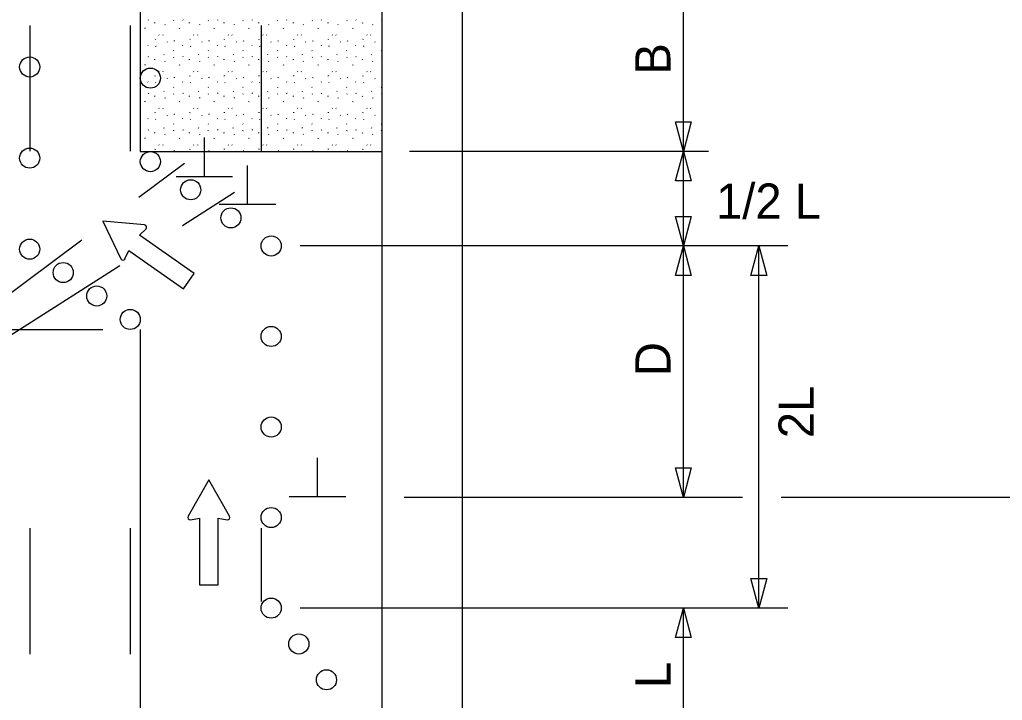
# Model space of a CAD drawing. Extents: x 16748 to 18475, y 7008 to 8262.
# Drawn here: x 17041.1 to 17236.5, y 7634.3 to 7769.6 of the extents above; entities that cross this region are included whole.
import ezdxf

# ---------------------------------------------------------------- set-up
doc = ezdxf.new("R2010")
doc.units = 0
for name, color, linetype in [('ALI_LEGAL_EX', 7, 'Continuous'), ('MT_SCRATCH_LEVEL_A', 7, 'Continuous'), ('MT_SCRATCH_LEVEL_E', 7, 'Continuous'), ('PAVT_EDGE_EX', 7, 'Continuous'), ('TRAFFIC_SIGNS_PR', 7, 'Continuous'), ('TYPICAL_TEXT_DIMEN_PR', 7, 'Continuous')]:
    doc.layers.add(name, color=color, linetype=linetype)

msp = doc.modelspace()

# ---------------------------------------------------------------- linework, layer by layer
at = {"layer": 'ALI_LEGAL_EX'}
for points in [[(17043.08, 7768.47), (17043.08, 7743.47)], [(17063.08, 7768.47), (17063.08, 7743.47)], [(17089.08, 7768.47), (17089.08, 7743.47)], [(17043.08, 7668.47), (17043.08, 7643.47)], [(17063.08, 7668.47), (17063.08, 7643.47)], [(17089.08, 7668.47), (17089.08, 7653.92)]]:
    msp.add_lwpolyline(points, dxfattribs=at)
at = {"layer": 'MT_SCRATCH_LEVEL_A'}
for p, q in [((17066.63, 7769.59), (17066.68, 7769.51)), ((17067.91, 7769.01), (17067.92, 7768.89)), ((17069.94, 7768.67), (17069.99, 7768.59)), ((17071.72, 7769.34), (17071.77, 7769.45)), ((17073.51, 7769.59), (17073.57, 7769.51)), ((17074.8, 7769.01), (17074.81, 7768.89)), ((17076.83, 7768.67), (17076.88, 7768.59)), ((17078.6, 7769.34), (17078.66, 7769.45)), ((17080.4, 7769.59), (17080.45, 7769.51)), ((17081.68, 7769.01), (17081.7, 7768.89)), ((17083.71, 7768.67), (17083.76, 7768.59)), ((17085.49, 7769.34), (17085.54, 7769.45)), ((17087.29, 7769.59), (17087.34, 7769.51)), ((17088.57, 7769.01), (17088.58, 7768.89)), ((17090.6, 7768.67), (17090.65, 7768.59)), ((17092.38, 7769.34), (17092.43, 7769.45)), ((17094.18, 7769.59), (17094.23, 7769.51)), ((17095.46, 7769.01), (17095.47, 7768.89)), ((17097.49, 7768.67), (17097.54, 7768.59)), ((17099.27, 7769.34), (17099.32, 7769.45)), ((17101.06, 7769.59), (17101.12, 7769.51)), ((17102.35, 7769.01), (17102.36, 7768.89)), ((17104.38, 7768.67), (17104.43, 7768.59)), ((17106.15, 7769.34), (17106.21, 7769.45)), ((17107.95, 7769.59), (17108, 7769.51)), ((17109.23, 7769.01), (17109.25, 7768.89)), ((17111.26, 7768.67), (17111.31, 7768.59)), ((17113.04, 7769.34), (17113.1, 7769.45)), ((17066.01, 7767.83), (17066.06, 7767.95)), ((17068.79, 7766.6), (17068.84, 7766.52)), ((17069.53, 7766.57), (17069.58, 7766.49)), ((17072.9, 7767.83), (17072.95, 7767.95)), ((17075.68, 7766.6), (17075.73, 7766.52)), ((17076.42, 7766.57), (17076.47, 7766.49)), ((17079.78, 7767.83), (17079.83, 7767.95)), ((17082.57, 7766.6), (17082.62, 7766.52)), ((17083.3, 7766.57), (17083.36, 7766.49)), ((17086.67, 7767.83), (17086.72, 7767.95)), ((17089.46, 7766.6), (17089.51, 7766.52)), ((17090.19, 7766.57), (17090.24, 7766.49)), ((17093.56, 7767.83), (17093.61, 7767.95)), ((17096.34, 7766.6), (17096.39, 7766.52)), ((17097.08, 7766.57), (17097.13, 7766.49)), ((17100.45, 7767.83), (17100.5, 7767.95)), ((17103.23, 7766.6), (17103.28, 7766.52)), ((17103.97, 7766.57), (17104.02, 7766.49)), ((17107.33, 7767.83), (17107.39, 7767.95)), ((17110.12, 7766.6), (17110.17, 7766.52)), ((17110.85, 7766.57), (17110.91, 7766.49)), ((17066.58, 7764.51), (17066.63, 7764.43)), ((17068.03, 7765.64), (17068.08, 7765.75)), ((17068.11, 7764.37), (17068.16, 7764.29)), ((17070.4, 7765.19), (17070.45, 7765.11)), ((17071.85, 7765.34), (17071.9, 7765.46)), ((17073.47, 7764.51), (17073.52, 7764.43)), ((17074.92, 7765.64), (17074.97, 7765.75)), ((17075, 7764.37), (17075.05, 7764.29)), ((17077.28, 7765.19), (17077.34, 7765.11)), ((17078.74, 7765.34), (17078.79, 7765.46)), ((17080.35, 7764.51), (17080.4, 7764.43)), ((17081.8, 7765.64), (17081.85, 7765.75)), ((17081.88, 7764.37), (17081.94, 7764.29)), ((17084.17, 7765.19), (17084.22, 7765.11)), ((17085.62, 7765.34), (17085.67, 7765.46)), ((17087.24, 7764.51), (17087.29, 7764.43)), ((17088.69, 7765.64), (17088.74, 7765.75)), ((17088.77, 7764.37), (17088.82, 7764.29)), ((17091.06, 7765.19), (17091.11, 7765.11)), ((17092.51, 7765.34), (17092.56, 7765.46)), ((17094.13, 7764.51), (17094.18, 7764.43)), ((17095.58, 7765.64), (17095.63, 7765.75)), ((17095.66, 7764.37), (17095.71, 7764.29)), ((17097.95, 7765.19), (17098, 7765.11)), ((17099.4, 7765.34), (17099.45, 7765.46)), ((17101.02, 7764.51), (17101.07, 7764.43)), ((17102.47, 7765.64), (17102.52, 7765.75)), ((17102.55, 7764.37), (17102.6, 7764.29)), ((17104.84, 7765.19), (17104.89, 7765.11)), ((17106.28, 7765.34), (17106.34, 7765.46)), ((17107.9, 7764.51), (17107.96, 7764.43)), ((17109.35, 7765.64), (17109.4, 7765.75)), ((17109.43, 7764.37), (17109.49, 7764.29)), ((17111.72, 7765.19), (17111.78, 7765.11)), ((17069.75, 7762.58), (17069.8, 7762.7)), ((17071.67, 7763.45), (17071.73, 7763.37)), ((17076.64, 7762.58), (17076.69, 7762.7)), ((17078.56, 7763.45), (17078.61, 7763.37)), ((17083.53, 7762.58), (17083.58, 7762.7)), ((17085.45, 7763.45), (17085.5, 7763.37)), ((17090.41, 7762.58), (17090.46, 7762.7)), ((17092.34, 7763.45), (17092.39, 7763.37)), ((17097.3, 7762.58), (17097.35, 7762.7)), ((17099.22, 7763.45), (17099.28, 7763.37)), ((17104.19, 7762.58), (17104.24, 7762.7)), ((17106.11, 7763.45), (17106.16, 7763.37)), ((17111.08, 7762.58), (17111.13, 7762.7)), ((17113, 7763.45), (17113.05, 7763.37)), ((17066.01, 7760.55), (17066.06, 7760.67)), ((17066.63, 7762.3), (17066.68, 7762.22)), ((17067.91, 7761.73), (17067.92, 7761.61)), ((17069.94, 7761.38), (17069.99, 7761.31)), ((17071.72, 7762.05), (17071.77, 7762.17)), ((17072.9, 7760.55), (17072.95, 7760.67)), ((17073.51, 7762.3), (17073.57, 7762.22)), ((17074.8, 7761.73), (17074.81, 7761.61)), ((17076.83, 7761.38), (17076.88, 7761.31)), ((17078.6, 7762.05), (17078.66, 7762.17)), ((17079.78, 7760.55), (17079.83, 7760.67)), ((17080.4, 7762.3), (17080.45, 7762.22)), ((17081.68, 7761.73), (17081.7, 7761.61)), ((17083.71, 7761.38), (17083.76, 7761.31)), ((17085.49, 7762.05), (17085.54, 7762.17)), ((17086.67, 7760.55), (17086.72, 7760.67)), ((17087.29, 7762.3), (17087.34, 7762.22)), ((17088.57, 7761.73), (17088.58, 7761.61)), ((17090.6, 7761.38), (17090.65, 7761.31)), ((17092.38, 7762.05), (17092.43, 7762.17)), ((17093.56, 7760.55), (17093.61, 7760.67)), ((17094.18, 7762.3), (17094.23, 7762.22)), ((17095.46, 7761.73), (17095.47, 7761.61)), ((17097.49, 7761.38), (17097.54, 7761.31)), ((17099.27, 7762.05), (17099.32, 7762.17)), ((17100.45, 7760.55), (17100.5, 7760.67)), ((17101.06, 7762.3), (17101.12, 7762.22)), ((17102.35, 7761.73), (17102.36, 7761.61)), ((17104.38, 7761.38), (17104.43, 7761.31)), ((17106.15, 7762.05), (17106.21, 7762.17)), ((17107.33, 7760.55), (17107.39, 7760.67)), ((17107.95, 7762.3), (17108, 7762.22)), ((17109.23, 7761.73), (17109.25, 7761.61)), ((17111.26, 7761.38), (17111.31, 7761.31)), ((17113.04, 7762.05), (17113.1, 7762.17)), ((17068.79, 7759.31), (17068.84, 7759.24)), ((17069.53, 7759.28), (17069.58, 7759.2)), ((17075.68, 7759.31), (17075.73, 7759.24)), ((17076.42, 7759.28), (17076.47, 7759.2)), ((17082.57, 7759.31), (17082.62, 7759.24)), ((17083.3, 7759.28), (17083.36, 7759.2)), ((17089.46, 7759.31), (17089.51, 7759.24)), ((17090.19, 7759.28), (17090.24, 7759.2)), ((17096.34, 7759.31), (17096.39, 7759.24)), ((17097.08, 7759.28), (17097.13, 7759.2)), ((17103.23, 7759.31), (17103.28, 7759.24)), ((17103.97, 7759.28), (17104.02, 7759.2)), ((17110.12, 7759.31), (17110.17, 7759.24)), ((17110.85, 7759.28), (17110.91, 7759.2)), ((17066.58, 7757.23), (17066.63, 7757.15)), ((17068.03, 7758.35), (17068.08, 7758.47)), ((17068.11, 7757.09), (17068.16, 7757.01)), ((17070.4, 7757.9), (17070.45, 7757.83)), ((17071.85, 7758.06), (17071.9, 7758.17)), ((17073.47, 7757.23), (17073.52, 7757.15)), ((17074.92, 7758.35), (17074.97, 7758.47)), ((17075, 7757.09), (17075.05, 7757.01)), ((17077.28, 7757.9), (17077.34, 7757.83)), ((17078.74, 7758.06), (17078.79, 7758.17)), ((17080.35, 7757.23), (17080.4, 7757.15)), ((17081.8, 7758.35), (17081.85, 7758.47)), ((17081.88, 7757.09), (17081.94, 7757.01)), ((17084.17, 7757.9), (17084.22, 7757.83)), ((17085.62, 7758.06), (17085.67, 7758.17)), ((17087.24, 7757.23), (17087.29, 7757.15)), ((17088.69, 7758.35), (17088.74, 7758.47)), ((17088.77, 7757.09), (17088.82, 7757.01)), ((17091.06, 7757.9), (17091.11, 7757.83)), ((17092.51, 7758.06), (17092.56, 7758.17)), ((17094.13, 7757.23), (17094.18, 7757.15)), ((17095.58, 7758.35), (17095.63, 7758.47)), ((17095.66, 7757.09), (17095.71, 7757.01)), ((17097.95, 7757.9), (17098, 7757.83)), ((17099.4, 7758.06), (17099.45, 7758.17)), ((17101.02, 7757.23), (17101.07, 7757.15)), ((17102.47, 7758.35), (17102.52, 7758.47)), ((17102.55, 7757.09), (17102.6, 7757.01)), ((17104.84, 7757.9), (17104.89, 7757.83)), ((17106.28, 7758.06), (17106.34, 7758.17)), ((17107.9, 7757.23), (17107.96, 7757.15)), ((17109.35, 7758.35), (17109.4, 7758.47)), ((17109.43, 7757.09), (17109.49, 7757.01)), ((17111.72, 7757.9), (17111.78, 7757.83)), ((17066.63, 7755.02), (17066.68, 7754.94)), ((17069.75, 7755.3), (17069.8, 7755.41)), ((17071.67, 7756.17), (17071.73, 7756.09)), ((17071.72, 7754.77), (17071.77, 7754.88)), ((17073.51, 7755.02), (17073.57, 7754.94)), ((17076.64, 7755.3), (17076.69, 7755.41)), ((17078.56, 7756.17), (17078.61, 7756.09)), ((17078.6, 7754.77), (17078.66, 7754.88)), ((17080.4, 7755.02), (17080.45, 7754.94)), ((17083.53, 7755.3), (17083.58, 7755.41)), ((17085.45, 7756.17), (17085.5, 7756.09)), ((17085.49, 7754.77), (17085.54, 7754.88)), ((17087.29, 7755.02), (17087.34, 7754.94)), ((17090.41, 7755.3), (17090.46, 7755.41)), ((17092.34, 7756.17), (17092.39, 7756.09)), ((17092.38, 7754.77), (17092.43, 7754.88)), ((17094.18, 7755.02), (17094.23, 7754.94)), ((17097.3, 7755.3), (17097.35, 7755.41)), ((17099.22, 7756.17), (17099.28, 7756.09)), ((17099.27, 7754.77), (17099.32, 7754.88)), ((17101.06, 7755.02), (17101.12, 7754.94)), ((17104.19, 7755.3), (17104.24, 7755.41)), ((17106.11, 7756.17), (17106.16, 7756.09)), ((17106.15, 7754.77), (17106.21, 7754.88)), ((17107.95, 7755.02), (17108, 7754.94)), ((17111.08, 7755.3), (17111.13, 7755.41)), ((17113, 7756.17), (17113.05, 7756.09)), ((17113.04, 7754.77), (17113.1, 7754.88)), ((17066.01, 7753.26), (17066.06, 7753.38)), ((17067.91, 7754.44), (17067.92, 7754.32)), ((17069.94, 7754.1), (17069.99, 7754.02)), ((17072.9, 7753.26), (17072.95, 7753.38)), ((17074.8, 7754.44), (17074.81, 7754.32)), ((17076.83, 7754.1), (17076.88, 7754.02)), ((17079.78, 7753.26), (17079.83, 7753.38)), ((17081.68, 7754.44), (17081.7, 7754.32)), ((17083.71, 7754.1), (17083.76, 7754.02)), ((17086.67, 7753.26), (17086.72, 7753.38)), ((17088.57, 7754.44), (17088.58, 7754.32)), ((17090.6, 7754.1), (17090.65, 7754.02)), ((17093.56, 7753.26), (17093.61, 7753.38)), ((17095.46, 7754.44), (17095.47, 7754.32)), ((17097.49, 7754.1), (17097.54, 7754.02)), ((17100.45, 7753.26), (17100.5, 7753.38)), ((17102.35, 7754.44), (17102.36, 7754.32)), ((17104.38, 7754.1), (17104.43, 7754.02)), ((17107.33, 7753.26), (17107.39, 7753.38)), ((17109.23, 7754.44), (17109.25, 7754.32)), ((17111.26, 7754.1), (17111.31, 7754.02)), ((17068.03, 7751.07), (17068.08, 7751.18)), ((17068.79, 7752.03), (17068.84, 7751.95)), ((17069.53, 7752), (17069.58, 7751.92)), ((17071.85, 7750.77), (17071.9, 7750.89)), ((17074.92, 7751.07), (17074.97, 7751.18)), ((17075.68, 7752.03), (17075.73, 7751.95)), ((17076.42, 7752), (17076.47, 7751.92)), ((17078.74, 7750.77), (17078.79, 7750.89)), ((17081.8, 7751.07), (17081.85, 7751.18)), ((17082.57, 7752.03), (17082.62, 7751.95)), ((17083.3, 7752), (17083.36, 7751.92)), ((17085.62, 7750.77), (17085.67, 7750.89)), ((17088.69, 7751.07), (17088.74, 7751.18)), ((17089.46, 7752.03), (17089.51, 7751.95)), ((17090.19, 7752), (17090.24, 7751.92)), ((17092.51, 7750.77), (17092.56, 7750.89)), ((17095.58, 7751.07), (17095.63, 7751.18)), ((17096.34, 7752.03), (17096.39, 7751.95)), ((17097.08, 7752), (17097.13, 7751.92)), ((17099.4, 7750.77), (17099.45, 7750.89)), ((17102.47, 7751.07), (17102.52, 7751.18)), ((17103.23, 7752.03), (17103.28, 7751.95)), ((17103.97, 7752), (17104.02, 7751.92)), ((17106.28, 7750.77), (17106.34, 7750.89)), ((17109.35, 7751.07), (17109.4, 7751.18)), ((17110.12, 7752.03), (17110.17, 7751.95)), ((17110.85, 7752), (17110.91, 7751.92)), ((17066.58, 7749.94), (17066.63, 7749.86)), ((17068.11, 7749.8), (17068.16, 7749.72)), ((17070.4, 7750.62), (17070.45, 7750.54)), ((17071.67, 7748.88), (17071.73, 7748.8)), ((17073.47, 7749.94), (17073.52, 7749.86)), ((17075, 7749.8), (17075.05, 7749.72)), ((17077.28, 7750.62), (17077.34, 7750.54)), ((17078.56, 7748.88), (17078.61, 7748.8)), ((17080.35, 7749.94), (17080.4, 7749.86)), ((17081.88, 7749.8), (17081.94, 7749.72)), ((17084.17, 7750.62), (17084.22, 7750.54)), ((17085.45, 7748.88), (17085.5, 7748.8)), ((17087.24, 7749.94), (17087.29, 7749.86)), ((17088.77, 7749.8), (17088.82, 7749.72)), ((17091.06, 7750.62), (17091.11, 7750.54)), ((17092.34, 7748.88), (17092.39, 7748.8)), ((17094.13, 7749.94), (17094.18, 7749.86)), ((17095.66, 7749.8), (17095.71, 7749.72)), ((17097.95, 7750.62), (17098, 7750.54)), ((17099.22, 7748.88), (17099.28, 7748.8)), ((17101.02, 7749.94), (17101.07, 7749.86)), ((17102.55, 7749.8), (17102.6, 7749.72)), ((17104.84, 7750.62), (17104.89, 7750.54)), ((17106.11, 7748.88), (17106.16, 7748.8)), ((17107.9, 7749.94), (17107.96, 7749.86)), ((17109.43, 7749.8), (17109.49, 7749.72)), ((17111.72, 7750.62), (17111.78, 7750.54)), ((17113, 7748.88), (17113.05, 7748.8)), ((17066.63, 7747.73), (17066.68, 7747.65)), ((17067.91, 7747.16), (17067.92, 7747.04)), ((17069.75, 7748.01), (17069.8, 7748.13)), ((17069.94, 7746.81), (17069.99, 7746.74)), ((17071.72, 7747.48), (17071.77, 7747.6)), ((17073.51, 7747.73), (17073.57, 7747.65)), ((17074.8, 7747.16), (17074.81, 7747.04)), ((17076.64, 7748.01), (17076.69, 7748.13)), ((17076.83, 7746.81), (17076.88, 7746.74)), ((17078.6, 7747.48), (17078.66, 7747.6)), ((17080.4, 7747.73), (17080.45, 7747.65)), ((17081.68, 7747.16), (17081.7, 7747.04)), ((17083.53, 7748.01), (17083.58, 7748.13)), ((17083.71, 7746.81), (17083.76, 7746.74)), ((17085.49, 7747.48), (17085.54, 7747.6)), ((17087.29, 7747.73), (17087.34, 7747.65)), ((17088.57, 7747.16), (17088.58, 7747.04)), ((17090.41, 7748.01), (17090.46, 7748.13)), ((17090.6, 7746.81), (17090.65, 7746.74)), ((17092.38, 7747.48), (17092.43, 7747.6)), ((17094.18, 7747.73), (17094.23, 7747.65)), ((17095.46, 7747.16), (17095.47, 7747.04)), ((17097.3, 7748.01), (17097.35, 7748.13)), ((17097.49, 7746.81), (17097.54, 7746.74)), ((17099.27, 7747.48), (17099.32, 7747.6)), ((17101.06, 7747.73), (17101.12, 7747.65)), ((17102.35, 7747.16), (17102.36, 7747.04)), ((17104.19, 7748.01), (17104.24, 7748.13)), ((17104.38, 7746.81), (17104.43, 7746.74)), ((17106.15, 7747.48), (17106.21, 7747.6)), ((17107.95, 7747.73), (17108, 7747.65)), ((17109.23, 7747.16), (17109.25, 7747.04)), ((17111.08, 7748.01), (17111.13, 7748.13)), ((17111.26, 7746.81), (17111.31, 7746.74)), ((17113.04, 7747.48), (17113.1, 7747.6)), ((17066.01, 7745.98), (17066.06, 7746.1)), ((17072.9, 7745.98), (17072.95, 7746.1)), ((17079.78, 7745.98), (17079.83, 7746.1)), ((17086.67, 7745.98), (17086.72, 7746.1)), ((17093.56, 7745.98), (17093.61, 7746.1)), ((17100.45, 7745.98), (17100.5, 7746.1)), ((17107.33, 7745.98), (17107.39, 7746.1)), ((17065.08, 7743.42), (17113.08, 7743.42)), ((17068.03, 7743.78), (17068.08, 7743.9)), ((17068.79, 7744.74), (17068.84, 7744.66)), ((17069.53, 7744.71), (17069.58, 7744.64)), ((17071.85, 7743.49), (17071.9, 7743.6)), ((17074.92, 7743.78), (17074.97, 7743.9)), ((17075.68, 7744.74), (17075.73, 7744.66)), ((17076.42, 7744.71), (17076.47, 7744.64)), ((17078.74, 7743.49), (17078.79, 7743.6)), ((17081.8, 7743.78), (17081.85, 7743.9)), ((17082.57, 7744.74), (17082.62, 7744.66)), ((17083.3, 7744.71), (17083.36, 7744.64)), ((17085.62, 7743.49), (17085.67, 7743.6)), ((17088.69, 7743.78), (17088.74, 7743.9)), ((17089.46, 7744.74), (17089.51, 7744.66)), ((17090.19, 7744.71), (17090.24, 7744.64)), ((17092.51, 7743.49), (17092.56, 7743.6)), ((17095.58, 7743.78), (17095.63, 7743.9)), ((17096.34, 7744.74), (17096.39, 7744.66)), ((17097.08, 7744.71), (17097.13, 7744.64)), ((17099.4, 7743.49), (17099.45, 7743.6)), ((17102.47, 7743.78), (17102.52, 7743.9)), ((17103.23, 7744.74), (17103.28, 7744.66)), ((17103.97, 7744.71), (17104.02, 7744.64)), ((17106.28, 7743.49), (17106.34, 7743.6)), ((17109.35, 7743.78), (17109.4, 7743.9)), ((17110.12, 7744.74), (17110.17, 7744.66)), ((17110.85, 7744.71), (17110.91, 7744.64))]:
    msp.add_line(p, q, dxfattribs=at)
at = {"layer": 'MT_SCRATCH_LEVEL_E'}
for p, q in [((17057.62, 7729.55), (17061.2, 7722.04)), ((17065.93, 7728.81), (17057.62, 7729.55)), ((17057.62, 7729.55), (17061.2, 7722.04)), ((17065.93, 7728.81), (17057.62, 7729.55)), ((17064.94, 7726.75), (17066.21, 7728.02)), ((17064.94, 7726.75), (17066.21, 7728.02)), ((17075.81, 7719.16), (17064.94, 7726.75)), ((17075.81, 7719.16), (17064.94, 7726.75)), ((17062.03, 7722.04), (17062.79, 7723.68)), ((17062.03, 7722.04), (17062.79, 7723.68)), ((17062.79, 7723.68), (17073.66, 7716.09)), ((17062.79, 7723.68), (17073.66, 7716.09)), ((17073.66, 7716.09), (17075.81, 7719.16)), ((17073.66, 7716.09), (17075.81, 7719.16)), ((17078.69, 7678.1), (17074.58, 7670.86)), ((17078.69, 7678.1), (17074.58, 7670.86)), ((17082.83, 7670.86), (17078.69, 7678.1)), ((17082.83, 7670.86), (17078.69, 7678.1)), ((17075.06, 7670.18), (17076.84, 7670.49)), ((17075.06, 7670.18), (17076.84, 7670.49)), ((17076.84, 7670.49), (17076.84, 7657.24)), ((17076.84, 7670.49), (17076.84, 7657.24)), ((17080.58, 7657.24), (17080.58, 7670.49)), ((17080.58, 7670.49), (17082.36, 7670.18)), ((17080.58, 7657.24), (17080.58, 7670.49)), ((17080.58, 7670.49), (17082.36, 7670.18)), ((17076.84, 7657.24), (17080.58, 7657.24)), ((17076.84, 7657.24), (17080.58, 7657.24))]:
    msp.add_line(p, q, dxfattribs=at)
for centre, start, end in [((17065.88, 7728.34), 315.105, 84.8419), ((17065.88, 7728.34), 315.105, 84.8419), ((17061.62, 7722.24), 205.4936, 335.0326), ((17061.62, 7722.24), 205.4936, 335.0326), ((17074.99, 7670.64), 150.4248, 279.9638), ((17074.99, 7670.64), 150.4248, 279.9638), ((17082.43, 7670.64), 260.0362, 29.7731), ((17082.43, 7670.64), 260.0362, 29.7731)]:
    msp.add_arc(centre, 0.463, start, end, dxfattribs=at)
at = {"layer": 'PAVT_EDGE_EX'}
for p, q in [((17113.08, 8185.96), (17113.08, 7352.54)), ((17129.08, 8185.96), (17129.08, 7352.54)), ((17065.08, 7859.65), (17065.08, 7743.42)), ((17065.08, 7708), (17065.08, 7352.54))]:
    msp.add_line(p, q, dxfattribs=at)
at = {"layer": 'TRAFFIC_SIGNS_PR'}
for centre in [(17043.08, 7760.19), (17067.08, 7757.98), (17043.08, 7742.08), (17067.08, 7741.37), (17075.1, 7735.78), (17083.1, 7730.19), (17043.08, 7723.97), (17091.1, 7724.61), (17049.75, 7719.31), (17056.41, 7714.66), (17063.08, 7710), (17091.1, 7706.61), (17091.1, 7688.61), (17091.1, 7670.61), (17091.1, 7652.61), (17096.6, 7645.47), (17102.1, 7638.35)]:
    msp.add_circle(centre, 2, dxfattribs=at)
at = {"layer": 'TYPICAL_TEXT_DIMEN_PR'}
for p, q in [((17173.08, 7743.42), (17173.08, 7775.48)), ((17173.08, 7743.42), (17171.51, 7749.28)), ((17171.51, 7749.28), (17173.08, 7749.28)), ((17173.08, 7749.28), (17174.65, 7749.28)), ((17174.65, 7749.28), (17173.08, 7743.42)), ((17077.82, 7738.35), (17077.82, 7746.14)), ((17178.08, 7743.42), (17118.58, 7743.42)), ((17171.51, 7737.56), (17173.08, 7743.42)), ((17173.08, 7743.42), (17174.65, 7737.56)), ((17173.08, 7724.61), (17173.08, 7743.42)), ((17064.77, 7734.3), (17073.87, 7741.08)), ((17086.42, 7732.84), (17086.42, 7740.62)), ((17083.44, 7738.35), (17072.19, 7738.35)), ((17173.08, 7737.56), (17171.51, 7737.56)), ((17174.65, 7737.56), (17173.08, 7737.56)), ((17083.8, 7735.23), (17073.44, 7728.62)), ((17092.04, 7732.84), (17080.79, 7732.84)), ((17173.08, 7724.61), (17171.51, 7730.47)), ((17171.51, 7730.47), (17173.08, 7730.47)), ((17173.08, 7730.47), (17174.65, 7730.47)), ((17174.65, 7730.47), (17173.08, 7724.61)), ((16961.04, 7656.9), (17053.42, 7725.82)), ((17193.82, 7724.61), (17096.85, 7724.61)), ((17171.51, 7718.74), (17173.08, 7724.61)), ((17173.08, 7674.61), (17173.08, 7724.61)), ((17173.08, 7724.61), (17174.65, 7718.74)), ((17186.51, 7718.74), (17188.08, 7724.61)), ((17188.08, 7652.61), (17188.08, 7724.61)), ((17188.08, 7724.61), (17189.65, 7718.74)), ((17061, 7720.68), (16961.04, 7656.9)), ((17173.08, 7718.74), (17171.51, 7718.74)), ((17174.65, 7718.74), (17173.08, 7718.74)), ((17188.08, 7718.74), (17186.51, 7718.74)), ((17189.65, 7718.74), (17188.08, 7718.74)), ((16927.98, 7708), (17057.62, 7708)), ((17100.32, 7674.72), (17100.32, 7682.5)), ((17173.08, 7674.61), (17171.51, 7680.47)), ((17171.51, 7680.47), (17173.08, 7680.47)), ((17173.08, 7680.47), (17174.65, 7680.47)), ((17174.65, 7680.47), (17173.08, 7674.61)), ((17105.95, 7674.72), (17094.7, 7674.72)), ((17184.84, 7674.61), (17117.53, 7674.61)), ((17242.95, 7674.61), (17192.54, 7674.61)), ((17188.08, 7652.61), (17186.51, 7658.47)), ((17186.51, 7658.47), (17188.08, 7658.47)), ((17188.08, 7658.47), (17189.65, 7658.47)), ((17189.65, 7658.47), (17188.08, 7652.61)), ((17193.82, 7652.61), (17096.85, 7652.61)), ((17171.51, 7646.74), (17173.08, 7652.61)), ((17173.08, 7622.09), (17173.08, 7652.61)), ((17173.08, 7652.61), (17174.65, 7646.74)), ((17173.08, 7646.74), (17171.51, 7646.74)), ((17174.65, 7646.74), (17173.08, 7646.74))]:
    msp.add_line(p, q, dxfattribs=at)

# ---------------------------------------------------------------- texts
for s, p in [('B', (17170.52, 7758.68)), ('D', (17170.52, 7698.73)), ('2L', (17199, 7686.39)), ('L', (17170.52, 7636.71))]:
    msp.add_text(s, height=7, rotation=90, dxfattribs=at).set_placement(p)
msp.add_text('1/2 L', height=7, dxfattribs=at).set_placement((17179.59, 7730.02))

doc.saveas('drawing.dxf')
